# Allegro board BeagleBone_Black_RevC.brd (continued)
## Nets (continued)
MII1_RXD0: R128.1 U5.M16
MII1_RXD1: R127.1 U5.L15
MII1_RXD2: R126.1 U5.L16
MII1_RXD3: R125.1 U5.L17
MII1_RXDV: R129.1 U5.J17
MII1_RXERR: R133.1 U5.J15
MII1_TXCLK: R134.1 U5.K18
MII1_TXD0: R39.1 U5.K17
MII1_TXD1: R40.1 U5.K16
MII1_TXD2: R41.1 U5.K15
MII1_TXD3: R42.1 U5.J18
MII1_TXEN: R38.1 U5.J16
MMC0_CD: P2.19 P10.10 R157.1 U5.C15
MMC0_CLKO: R16.1 U5.G17
MMC0_CMD: R15.1 U5.G18
MMC0_DAT0: R31.1 U5.G16
MMC0_DAT1: R32.1 U5.G15
MMC0_DAT2: R2.1 U5.F18
MMC0_DAT3: R13.1 U5.F17
MMC1_CLK: C175.1 P8.21 R35.2 R110.2 U13.M6
MMC1_CMD: P8.20 R36.2 R109.2 U13.M5
MMC1_DAT0: P8.25 R43.2 R101.2 U13.A3
MMC1_DAT1: P8.24 R44.2 R102.2 U13.A4
MMC1_DAT2: P8.5 R103.2 R168.2 U13.A5
MMC1_DAT3: P8.6 R104.2 R169.2 U13.B2
MMC1_DAT4: P8.23 R105.2 R170.2 U13.B3
MMC1_DAT5: P8.22 R106.2 R171.2 U13.B4
MMC1_DAT6: P8.3 R107.2 R172.2 U13.B5
MMC1_DAT7: P8.4 R108.2 R173.2 U13.B6
MODE2: R113.1 R138.2 U14.15
OSC0_IN: C25.1 R17.1 U5.V10 Y2.2
OSC0_OUT: C26.1 R17.2 U5.U11 Y2.1
OSC1_IN: C21.2 U5.A6 Y1.1
OSC1_OUT: C22.2 U5.A4 Y1.4
P_BYPASS: C4.2 U2.47
P_INT_LDO: C3.2 U2.48
P_L1: L1.1 U2.20
P_L2: L2.1 U2.23
P_L3: L3.1 U2.31
PHY_VDDCR: C134.1 C136.1 U14.6
PHY_XTAL1: C143.1 R141.2 R142.1 Y3.1
PHY_XTAL2: R141.1 R143.1 U14.4(XTAL2)
PHYX: C142.1 R143.2 Y3.2
PMIC_INT: R1.2 U2.45 U5.B18
PMIC_PGOOD: U2.26 U5.B15 U16.2
PMIC_POWR_EN: U2.9 U5.C6
PROC_A15: R18.1 U5.A15
PWR_BUT: P9.9 S3.2 S3.4(B2) U2.25
PWR_LEDR: D1.1(C) R12.2
RBIAS: R144.1 U14.32
RCLKIN: R140.2 R142.2 U14.5
REFCLKO: R118.1 R124.2 R131.2 U14.7
RXD0/MODE0: R112.1 R128.2 U14.11
RXD1/MODE1: R114.1 R127.2 U14.10
RXD2/RMIISEL: R117.1 R126.2 U14.9
RXD3/PHYAD2: R116.1 R125.2 U14.8
RXDV: R129.2 U14.26
RXER/PHYAD0: R115.1 R133.2 U14.13
RXN: C138.1 P5.2 R121.1 U14.30
RXP: C137.1 P5.1 R120.1 U14.31
SD_CLK: C5.1 P10.5 R16.2 R152.2
SD_CMD: P10.3 R15.2 R151.2
SD_DAT0: P10.7 R31.2 R153.2
SD_DAT1: P10.8 R32.2 R154.2
SD_DAT2: P10.1 R2.2 R150.2
SD_DAT3: P10.2 R13.2 R155.2
SPI1_CS0: P9.28 U5.C12 U11.25
SPI1_D0: P9.29 U5.B13 U11.24
SPI1_D1: P9.30 U5.D12
SPI1_SCLK: P9.31 U5.A13 U11.23
SYS_5V: C7.2 C8.2 C10.2 C13.2 C17.1 C34.1 P9.7 P9.8 R71.1 R72.1 R73.1 R74.1 RT1.1 U2.2 U2.7 U2.8 U2.21 U2.22 U2.32 U2.39 U2.42 U4.2 U8.2 U8.3
SYS_RESETN: C24.1 C30.1 P2.15 P9.10 R14.2 S1.2 S1.4(B2) U1.2 U5.A10 U16.4(Y)
TCT_RCT: C141.1 P5.4 P5.5 R137.1
TESTOUT: TP3.1(TP) U5.A3
TIMER4: P8.7 U5.R7
TIMER5: P8.9 U5.T6
TIMER6: P8.10 U5.U6
TIMER7: P8.8 U5.T7
TXCLK: R134.2 U14.20
TXD0: R39.2 U14.22
TXD1: R40.2 U14.23
TXD2: R41.2 U14.24
TXD3: R42.2 U14.25
TXEN: R38.2 U14.21
TXN: C140.1 P5.6 R123.1 U14.28
TXP: C139.1 P5.3 R122.1 U14.29
U5_H18: R28.1 U5.H18
U5_R13: R160.1 U5.R13
U5_T13: R161.1 U5.T13
UART0_RX: U5.E15 U15.6
UART0_TX: U5.E16 U15.5
UART1_RXD: P9.26 U5.D16
UART1_TXD: P9.24 U5.D15
UART2_RXD: P9.22 U5.A17
UART2_TXD: P9.21 U5.B17
UART4_RXD: P9.11 U5.T17
UART4_TXD: P9.13 U5.U17
USB0_DM: P4.2 U5.N18 U10.2
USB0_DP: P4.3 U5.N17 U10.1
USB0_ID: P4.4 U5.P16 U10.3
USB1_DM: P3.2 U5.R18 U9.2
USB1_DP: P3.3 U5.R17 U9.1
USB1_DRVVBUS: R53.1 U5.F15 U8.4
USB1_ID: R49.2 U5.P17
USB1_OCN: R52.2 U5.T16 U8.5
USB1_PWR: C35.1 FB7.1 R37.2 U8.6 U8.7 U8.8 U9.6(VBUS)
USB1_VBUS: R37.1 U5.T18
USB_DC: C1.2 C36.1 P4.1(VB) R159.1 U2.12 U10.6(VBUS)
USR0: Q1.2 R76.1 U5.V15
USR1: Q1.5 R77.1 U5.U15
USR2: Q2.2 R78.1 U5.T15
USR3: Q2.5 R79.1 U5.V16
VDCDC1: L1.2 R6.1 U2.19
VIO: R7.2 U2.18 U16.5
VLDO1: R5.1 R7.1 R8.1 U2.3
VREFP_ADC: C31.1 C32.1 C33.1 R27.2 U5.B9
VRTC: C16.1 C105.1 R5.2 R26.1 U5.D7
WAKEUP: R26.2 U2.13(WAKEUP) U5.C5
WP: R156.2 TP4.1(TP) U7.5(WP)
XDMA_EVENT_INTR0: P2.17 R18.2 U6.1
YEL_C: P5.11(YELC) R130.2
YELA: P5.12 R135.1 U14.2
ZQ: R99.2 U12.L8(ZQ)
N21667305: R149.1 U11.49
N21757673: C19.1 R10.1 R11.2 U4.4
N21769115: R75.2 S2.1 S2.3
N22155575: R159.2 U5.P15
N22248684: R167.1 Y4.3
N22248838: R21.1 U6.5
N22287501: R162.1 U3.4(Y)
N22287555: U3.2 U5.R14
N22420400: TP5.1(TP) U2.4 U2.5
N22420444: TP6.1(TP) U2.6
N22420447: TP7.1(TP) U2.11
N22488252: TP9.1(TP) U5.E17

Pads without a net: D6 6 7 9 10; D7 6 7 9 10; J1 2 3 6; NOREF 1; NOREF#3 1; NOREF#14 1; NOREF#26 1; NOREF#27 1; NOREF#29 1; P1 3; P2 6; P5 7; P6 2; P10 S2; U2 14 15 16 17 33 34 35 36 37 38 44; U3 1; U5 F16 M5 M15 P18; U9 3 5; U10 5; U11 26 28; U12 J1 J9 L1 L9; U13 A1 A2 A7 A8 A9 A10 A11 A12 A13 A14 B1 B7 B8 B9 B10 B11 B12 B13 B14 C1 C3 C5 C7 C8 C9 C10 C11 C12 C13 C14 D1 D2 D3 D4 D12 D13 D14 E1 E2 E3 E5 E8 E9 E10 E12 E13 E14 F1 F2 F3 F10 F12 F13 F14 G1 G2 G3 G10 G12 G13 G14 H1 H2 H3 H5 H12 H13 H14 J1 J2 J3 J12 J13 J14 K1 K2 K3 K6 K7 K10 K12 K13 K14 L1 L2 L3 L12 L13 L14 M1 M2 M3 M7 M8 M9 M10 M11 M12 M13 M14 N1 N3 N6 N7 N8 N9 N10 N11 N12 N13 N14 P1 P2 P7 P8 P9 P10 P11 P12 P13 P14; U16 1; Y1 2 3

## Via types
v1: diameter 0.457, hole 0.203, TOP to BOTTOM, 801 vias
v2: diameter 0.254, hole 0.152, TOP to BOTTOM, 29 vias
v3: diameter 0.559, hole 0.305, TOP to BOTTOM, 30 vias

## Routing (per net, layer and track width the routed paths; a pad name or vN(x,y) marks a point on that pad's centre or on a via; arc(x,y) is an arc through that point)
DGND: length 496.4
  TOP w0.121: U13.N2 v2(26.85,44.91)
  TOP w0.191: R118.2 31.43,26.48 32.95,26.48 v1(33.02,26.54) ; U10.4 v1(14.1,41.41)
  TOP w0.203: v3(23.88,15.24) 24.26,15.24 24.46,15.04 U2.30 ; U13.K8 v2(28.09,41.66) ; v1(12.37,44.77) Q1.1 12.37,46.21 12.51,46.35 13.53,46.35 13.67,46.5 Q1.4 ; U2.41 v1(23.46,19.62) ; U13.A6 33.54,42.66 33.66,42.55 33.66,41.27 v1(34.29,40.64) ; U13.J5 29.46,42.8 29.73,42.8 U13.G5 v2(30.09,43.66) ; Q2.4 10.17,46.5 10.03,46.35 9.02,46.35 8.88,46.21 Q2.1 v1(8.88,44.77) ; U13.C4 v2(31.6,43.16) ; U13.E7 v2(31.6,42.16) ; v2(26.04,43.66) U13.P4 ; U13.P6 v2(26.05,42.66) ; U13.N5 v2(26.85,43.41) ; U13.H10 v2(29.6,40.13)
  TOP w0.254: U5.L10 v1(44.92,30.01) ; v1(44.92,30.01) U5.K10 ; v1(44.92,30.01) U5.K11 ; v1(60.7,27.17) U12.E1 60.18,27.69 59.69,27.69 59.31,27.3 59.31,26.96 U12.G1 ; U5.L13 v1(43.32,30.81) U5.L12 ; U5.H7 v1(48.12,27.61) ; v3(65.41,41.91) 65.25,42.06 U11.53 ; U12.D1 v1(60.7,27.97) U12.E2 ; U5.M8 v1(46.52,31.61) U5.M9 ; v1(66.3,23.96) U12.J8 ; v1(66.3,27.97) U12.E8 ; v1(43.32,26.81) U5.G12 43.88,27.05 44.36,27.05 U5.G11 ; U5.M7 v1(48.12,30.81) U5.M6 ; v1(75.06,39.62) 74.93,39.5 74.55,39.5 74.42,39.37 D7.3 ; U5.J6 v1(48.92,28.41) U5.H6 ; U11.16 59.15,35.65 ; 59.15,35.65 U11.17 ; 59.15,35.65 59.05,35.56 v1(58.42,35.56) ; U5.N14 v1(41.72,31.61) U5.M14 ; D7.8 v1(78.99,39.37) ; U12.B9 v1(67.1,30.37) U12.A9 ; U5.N10 v1(44.92,32.41) U5.N11 ; v1(59.9,30.37) U12.B1 ; v1(59.9,21.56) U12.M1 ; D6.8 v1(78.99,34.92) ; v1(46.52,30.01) U5.K9 ; v1(67.1,19.96) U12.P9 ; v1(66.3,28.77) U12.D8 ; U11.8 61.21,40.25 v3(61.59,40.64) ; v1(44.92,31.61) U5.M10 ; U5.A1 v1(52.52,21.72) ; U5.G9 v1(46.52,26.81) U5.F8 ; v1(59.9,18.36) U12.T1 ; v1(67.1,18.36) U12.T9 ; v1(66.3,26.37) U12.G8 ; U11.9 61.21,39.76 v3(61.59,39.37) ; v1(67.1,21.56) U12.M9 ; v3(64.14,41.91) 64.75,42.52 U11.54 ; U5.H10 v1(44.92,28.41) U5.J10 ; v1(43.32,27.61) U5.H12 ; U5.A18 v1(38.52,22.01) ; U11.18 60.25,35 v1(60.45,34.8) 60.45,34.82 60.75,35.12 U11.19 ; U5.H9 v1(46.52,27.61) U5.G8 ; v3(61.59,41.91) 61.59,42.93 61.25,43.27 U11.61 ; v3(61.59,41.91) 60.75,42.76 U11.62 ; v3(61.59,41.91) 60.71,41.91 60.25,42.37 U11.63 ; U5.J11 v1(44.12,28.41) ; v1(47.32,28.41) U5.J8 ; U12.F9 v1(67.1,26.37) U12.G9 ; U5.M12 v1(44.12,30.81) U5.L11 ; D6.3 72.52,34.92 72.39,34.8 v1(72.01,34.8) ; v1(61.5,30.37) U12.B3 ; v1(47.32,27.61) U5.H8 ; v1(46.52,28.41) U5.J9 ; v1(59.9,19.96) U12.P1 ; v1(60.7,23.96) U12.J2 ; v1(48.12,32.41) U5.N7 ; U5.K7 U5.J7 v1(48.12,28.41) ; U5.V1 v1(52.52,36.7) ; U5.V18 v1(38.1,36.01)
  TOP w0.381: R93.2 R94.2 R95.2 v1(71.75,45.72) ; R93.2 R92.2 R91.2 R90.2 R89.2 R88.2 R87.2 R86.2 R85.2 R83.2 R82.2 R84.2 ; R93.2 v1(69.85,45.72) ; 14.92,19.37 C3.1 C18.2 C16.2 ; v1(34.29,6.48) C29.2 ; C169.2 56.9,36.83 57.15,37.08 v1(57.15,37.34) ; S1.1 v1(9.02,52.24) ; U3.3 v1(40.97,45.85) ; S2.4 S2.2 v1(78.49,42.38) ; v1(56.52,48.26) C57.1 56.13,47.5 55.88,47.24 55.88,46.74 55.63,46.48 C165.2 53.72,46.48 52.7,45.47 C168.2 ; R84.2 R80.2 R81.2 v1(57.47,45.72) ; R84.2 v1(59.37,45.72) ; C173.2 v1(74.68,46.48) ; Y4.2 41.71,40.82 ; Y4.2 40.56,40.82 ; Y4.2 41.15,41.53 ; S1.3 v1(6.86,52.24) ; v1(6.99,17.14) R10.2 C19.2 ; v1(56.26,11.68) 55.63,11.68 C155.1 C96.1 ; v1(53.98,42.67) C167.2 54.36,43.43 54.61,43.69 54.61,44.2 54.86,44.45 C156.2 ; C61.1 v1(72.71,48.26) ; C5.2 R118.2 ; 46.86,43.05 v1(46.86,43.7) ; v1(29.46,20.7) 28.77,21.4 C37.2 ; v1(45.09,12.7) C27.2 R165.2 ; C166.2 v1(52.7,41.66) ; S3.1 v1(7.62,42.71) S3.3 ; R29.2 v1(44.96,43.56) ; v1(55.24,39.12) C160.2 55.63,39.88 55.88,40.13 55.88,40.64 56.13,40.89 C163.2 ; v1(53.98,41.66) C157.2 ; U16.3 30.64,9.69 v1(30.16,10.16) ; R25.2 36.39,9.08 36.07,8.76 v1(36.07,8.57) ; v1(22.35,7.11) 22.35,8.51 C9.1 22.99,8 v1(22.99,7.11) v1(22.35,7.11) ; C12.1 24.83,8.45 v1(24.83,7.11) v1(24.19,7.11) 24.19,8.06 C12.1
  TOP w0.508: v1(29.97,18.03) v1(29.97,17.4) 29.97,16.13 ; v1(64.52,15.49) 64.52,13.78 C34.2 63.63,13.91 v1(63.63,15.49)
  TOP w0.635: 14.92,19.37 v1(13.97,19.37) C1.1
  TOP w0.762: C11.1 C55.1
  LYR2_GND w0.889: 4.09,9.53 P1.2 ; P1.2 5.18,11.63 ; P1.2 6.27,9.53 ; P1.2 5.18,7.42 ; 16.41,24.67 P5.8 ; P5.8 17.88,26.13 ; P5.8 16.41,26.13 ; P5.8 17.88,24.67 ; P9.46 76.3,3.71 ; P9.46 74.83,5.18 ; P9.46 76.3,5.18 ; P9.46 74.83,3.71 ; P8.1 20.65,51.13 ; P8.1 18.72,49.2 ; P8.1 18.72,51.13 ; P8.1 20.65,49.2 ; 18.95,3.71 P9.2 ; P9.2 20.42,5.18 ; P9.2 18.95,5.18 ; P9.2 20.42,3.71 ; 41.58,6.65 J1.1 ; J1.1 43.51,6.65 ; J1.1 41.58,8.59 ; 18.72,2.87 P9.1 20.65,2.87 ; P3.4 74.12,19.56 ; P3.4 74.12,21.11 ; P3.4 72.56,21.11 ; P3.4 72.56,19.56 ; 16.54,8.86 TP8.1 ; TP8.1 18.01,7.39 ; TP8.1 16.54,7.39 ; TP8.1 18.01,8.86 ; TP1.1 59.79,11.53 ; TP1.1 58.32,10.06 ; TP1.1 59.79,10.06 ; TP1.1 58.32,11.53 ; 72.29,3.71 P9.44 ; P9.44 73.76,5.18 ; P9.44 73.76,3.71 ; P9.44 72.29,5.18 ; 73.76,2.64 P9.43 72.29,2.64 ; 74.83,2.64 P9.45 76.3,2.64 ; 20.42,51.97 P8.2 18.95,51.97
  BOTTOM w0.191: 79.89,25.75 P6.13 79.16,25.75 v1(78.99,25.91) ; R115.2 30.99,32.1 30.86,32.23 29.34,32.23 29.21,32.35 v1(29.21,32.7) ; v1(82.8,26.73) 82.11,26.73 81.72,26.35 P6.16 ; 79.89,24.55 P6.7 v1(78.99,24.55) ; P6.4 81.72,23.95 82.04,23.62 v1(82.8,23.62) ; v1(44.92,24.41) 44.92,24.3 45.71,23.5 C88.2 ; P6.10 v1(82.8,25.15)
  BOTTOM w0.203: C100.2 48.81,25.94 49.26,25.5 49.43,25.5 v1(49.72,25.21) ; C135.2 26.92,33.91 26.92,36.2 26.29,36.83 25.74,36.83 25.27,37.3 C174.2
  BOTTOM w0.254: C130.2 v1(34.29,40.64) ; v2(31.6,42.16) 31.6,41.88 31.11,41.4 C129.2 ; U15.1 50.28,10.68 50.04,10.92 50.04,11.94 50.28,12.18 U15.4 52.08,12.18 52.83,11.43 52.83,10.54 53.21,10.16 v1(54.48,10.16) ; U6.4 44.79,12.41 v1(45.09,12.7) ; C127.2 v1(25.4,40.64) ; v2(28.09,41.66) 28.09,41.94 28.57,42.42 C128.2 ; C70.1 42.63,26.12 v1(43.32,26.81) v1(43.32,27.61) ; C155.1 56.01,11.94 v1(56.26,11.68)
  BOTTOM w0.305: U9.4 80.48,18.91 v1(80.62,19.05) ; C46.2 44.63,29.72 v1(44.92,30.01) ; C48.2 47.83,28.7 v1(48.12,28.41) ; C98.2 48.92,29.1 v1(48.92,28.41) ; C73.1 v1(48.12,32.41) 47.43,32.41 C43.2 ; C50.2 v1(47.32,27.61) ; v1(43.32,26.81) 44.01,26.81 C63.2 ; C72.1 46.23,26.52 v1(46.52,26.81) ; v1(46.52,31.61) 46.23,31.9 C42.2 ; C94.2 v1(44.12,30.81) ; v1(46.52,30.01) 45.83,30.01 C47.2 ; C49.2 45.58,28.41 v1(44.92,28.41) ; C99.2 v1(48.12,27.61) ; v1(48.12,30.81) C97.2 ; C41.2 41.72,32.3 v1(41.72,31.61) 41.72,30.92 C66.2 ; C60.1 v1(43.32,27.61)
  BOTTOM w0.381: C132.2 24.77,29.84 v3(25.08,30.16) 25.4,29.84 C136.2 C134.2 ; C132.2 C131.2 ; C132.2 24,30.99 v3(24.13,31.11) ; v1(8.88,44.77) 8.88,45.86 ; 8.88,45.86 7.23,45.86 7.11,45.73 P4.5 ; 8.88,45.86 8.88,46.56 ; v1(72.01,34.8) 71.77,34.56 P10.6 ; v3(25.08,32.07) 24.77,32.07 24.38,32.45 C133.1 ; C108.2 v1(57.15,29.57) ; C59.2 C90.2 C91.2 C89.2 C105.2 C92.2 ; C40.1 33.02,28.07 v1(33.02,27.37) 33.02,26.99 ; C40.1 33.78,28.07 C52.2 ; C40.1 33.78,28.83 C51.2 ; 8.88,46.56 8.88,47.37 8.85,47.4 v1(8.85,49.11) ; 8.88,46.56 8.89,46.55 R78.2 ; C23.2 v1(24.63,39.12) ; U8.1 v1(75.56,13.63) ; C161.2 C166.2 v1(52.7,41.66) ; C145.2 58.93,35.56 v1(58.42,35.56) ; R148.2 C151.2 66.42,35.69 66.04,36.07 66.04,36.32 65.66,36.7 C147.2 v3(65.41,38.1) ; C149.2 68.33,44.7 v1(68.58,44.7) ; 33.02,20.33 33.02,21.21 C62.1 33.78,21.21 33.78,20.33 ; 33.02,20.33 33.78,20.33 ; 33.02,20.33 v1(33.02,20.32) ; v1(6.22,29.46) v1(6.22,30.23) ; v1(6.22,29.46) 5.4,29.46 R136.1 5.4,30.23 v1(6.22,30.23) ; v1(6.22,29.46) R130.1 R135.2 ; v1(6.22,30.23) R132.1 ; v1(36.89,23.18) 36.89,23.18 37.21,22.86 C85.2 C83.2 C82.2 ; v3(64.14,41.91) 64.14,43.31 65.41,43.31 ; v1(47.32,38.1) C81.2 ; C78.2 35.05,33.91 v1(35.56,33.91) ; R12.1 4.83,16.51 5.46,17.14 v1(6.99,17.14) R10.2 ; C173.2 v1(74.68,46.48) ; U1.3 30.17,37.21 30.59,37.21 30.61,37.19 v1(30.71,37.19) ; v1(53.98,41.66) C157.2 C172.2 ; C24.2 C30.2 v1(30.16,10.16) ; v1(36.83,30.81) C87.2 C45.2 ; R96.1 v1(69.85,23.16) 70.36,23.16 70.41,23.11 C153.2 ; C140.2 v1(10.67,27.94) ; R53.2 v1(76.81,19.68) ; R117.2 R116.2 v1(31.75,27.94) ; C71.1 38.61,36.32 38.3,36.01 v1(38.1,36.01) 37.81,36.01 37.61,35.81 C86.2 ; C92.2 C104.2 v1(49.21,18.41) ; C92.2 v1(48.26,18.41) ; C139.2 v1(10.67,31.75) ; C152.2 v1(26.04,23.11) ; C154.2 70.45,26.16 ; C143.2 27.11,26.35 v1(28.26,26.35) ; C119.2 v1(69.85,24.36) ; R77.2 13.9,45.53 13.65,45.78 13.65,46.29 13.4,46.55 R76.2 12.6,46.55 12.37,46.32 v1(12.37,44.77) ; C54.2 C44.2 ; C54.2 C79.2 C69.1 ; C54.2 v1(36.83,26.81) ; v1(29.46,20.7) 29.46,21.46 29.91,21.91 U7.2 ; v1(49.21,18.41) 50.87,18.41 51.12,18.66 R54.1 ; v1(49.21,18.41) R164.2 ; C118.1 68.83,32.13 C114.2 68.83,30.35 69.09,30.1 C115.2 v1(69.85,29.57) 71.35,29.57 P10.9 ; C80.2 41.32,37.78 41.42,37.88 41.42,38.25 v1(41.53,38.35) ; C135.2 v1(28.45,33.66) ; C64.2 33.78,20.33 ; C113.2 v1(57.15,19.16) ; C39.1 33.78,25.15 C53.2 33.03,24.13 v1(32.89,24.27) ; C39.1 33.78,25.91 C52.2 ; C39.1 33.02,25.91 v1(33.02,26.54) 33.02,26.99 ; C125.2 v1(32.38,48.26) ; v1(66.3,23.96) U12.J8 C123.2 ; C121.2 v1(69.85,19.16) ; v1(33.02,35.56) C67.2 C38.2 ; C84.2 37.19,32.41 36.83,32.77 v1(36.83,33.15) 36.83,33.66 37.15,33.97 R49.1 ; C111.2 v1(57.15,23.16) ; C122.1 69.84,16.83 v1(69.85,16.82) ; P2.20 39.56,18.73 40.53,17.76 40.53,16.27 40.24,15.98 39.5,15.98 39.35,16.13 38.01,16.13 P2.16 v1(36.07,16.19) ; P2.8 36.13,11.11 v1(36.07,11.18) 36.07,12.13 36.32,12.38 P2.10 P2.12 ; C107.2 v1(57.15,31.17) ; 66.67,43.31 65.41,43.31 ; 65.41,43.31 v3(65.41,41.91) ; R99.1 v1(69.85,21.96) ; C58.2 C106.2 43.96,37.32 44.32,36.96 v1(45.72,36.96) C56.1 ; v1(10.79,44.77) R79.2 ; C126.1 v1(23.5,39.88) ; C120.2 v1(69.85,20.76) ; C141.2 v1(10.67,30.48) ; v1(40.97,45.85) 40.97,47.04 40.51,47.5 C158.2 ; v3(65.41,40.64) 65.66,40.39 C150.2 ; C117.2 v1(69.85,25.57) ; R22.1 v1(57.15,28.41) ; C52.2 33.02,26.99 ; P2.4 v1(36.07,8.57) ; C109.2 v1(57.15,27.17) C28.2 ; C164.2 v1(50.16,41.66) ; C74.1 50.52,37.74 v1(50.16,38.1) ; R145.2 v1(31.75,34.61) ; C57.1 v1(56.52,48.26) ; C101.2 52.07,18.67 52.32,18.41 v1(52.83,18.41) 53.72,18.41 C95.1 53.66,17.84 C102.2 C103.2 55.31,16.7 v1(55.37,16.76) ; C159.2 39.69,40.51 v1(40.32,39.88) ; C142.2 23.05,26.35 v1(21.91,26.35) ; C35.2 v1(81.89,19.68) ; C138.2 v1(10.67,33.02) ; C68.1 v1(48.92,38.1) ; v1(32.38,37.15) C77.2 ; C137.2 v1(10.67,34.29) ; R144.2 v1(18.73,28.26) ; C144.2 61.09,40.13 v3(61.59,40.64) ; C17.2 v1(6.99,15.88) ; C112.2 v1(57.15,20.76) ; C110.2 v1(57.15,25.57) ; v1(62.99,21.21) C124.2 R100.2 ; C61.1 v1(72.71,48.26) ; v1(14.1,41.41) 14.09,41.4 ; C116.2 v1(69.85,27.97) ; v1(44.2,14.1) v1(43.43,14.1) 43.43,14.86 FB3.2 44.2,14.86 v1(44.2,14.1)
  BOTTOM w0.508: C36.2 13.04,42.52 v1(12.34,43.22)
  BOTTOM w0.635: 16.45,14.61 14.22,14.61 13.97,14.86 13.97,15.88 ; 13.97,17.14 13.97,15.88 ; 13.97,17.14 16.45,17.14 ; 13.97,17.14 13.97,18.41 ; 13.97,15.88 U4.7 ; v1(13.97,19.37) 13.97,18.41 ; 13.97,18.41 U4.5 ; C2.1 5.71,12.45 5.18,11.91 P1.2
  BOTTOM w0.762: P9.1 P9.2 ; P9.45 P9.46 ; P8.1 P8.2
  vias: v1(7.79,48.97) v3(21.34,15.24) v3(21.34,13.97) v3(22.61,15.24) v3(22.61,13.97) v3(25.08,31.11) v3(26.04,31.11) v3(61.59,38.1) v3(62.87,41.91) v3(62.87,40.64) v3(62.87,39.37) v3(62.87,38.1) v3(64.14,40.64) v3(64.14,39.37) v3(64.14,38.1) v3(65.41,39.37) v3(78.71,15.24) v3(78.71,13.97) v3(79.98,15.24) v3(79.98,13.97)
GND_EARTH: length 144.8
  TOP w0.889: MTG3.1 16.37,53.2 ; MTG3.1 12.84,53.2 ; MTG3.1 12.84,49.67 ; MTG3.1 16.37,49.67 ; MTG1.1 16.37,4.94 ; MTG1.1 16.37,1.41 ; MTG1.1 12.84,4.94 ; MTG1.1 12.84,1.41 ; 78.88,50.03 MTG4.1 ; MTG4.1 78.88,46.49 ; MTG4.1 82.41,46.49 ; 78.88,8.12 MTG2.1 ; MTG2.1 78.88,4.58 ; MTG2.1 82.41,8.12
  LYR2_GND w0.889: 78.88,4.58 MTG2.1 ; MTG2.1 78.88,8.12 ; MTG2.1 82.41,8.12 ; MTG3.1 16.37,49.67 ; MTG3.1 12.84,49.67 ; MTG3.1 12.84,53.2 ; MTG3.1 16.37,53.2 ; 12.84,4.94 MTG1.1 ; MTG1.1 12.84,1.41 ; MTG1.1 16.37,1.41 ; MTG1.1 16.37,4.94 ; 78.88,50.03 MTG4.1 ; MTG4.1 82.41,46.49 ; MTG4.1 78.88,46.49
  LYR5_PWR w0.889: MTG3.1 16.37,53.2 ; MTG3.1 16.37,49.67 ; MTG3.1 12.84,49.67 ; MTG3.1 12.84,53.2 ; 12.84,1.41 MTG1.1 ; MTG1.1 12.84,4.94 ; MTG1.1 16.37,4.94 ; MTG1.1 16.37,1.41 ; 78.88,50.03 MTG4.1 ; MTG4.1 78.88,46.49 ; MTG4.1 82.41,46.49 ; 78.88,4.58 MTG2.1 ; MTG2.1 78.88,8.12 ; MTG2.1 82.41,8.12
  BOTTOM w0.381: v1(1.91,30.23) 2.86,30.23 R136.2 2.86,29.46 v1(1.91,29.46)
  BOTTOM w0.635: P10.S1 75.97,43.71 77.72,45.47
  BOTTOM w0.889: 78.88,8.12 MTG2.1 ; MTG2.1 82.41,8.12 ; MTG2.1 78.88,4.58 ; MTG4.1 82.41,46.49 ; MTG4.1 78.88,46.49 ; MTG4.1 78.88,50.03 ; 12.84,1.41 MTG1.1 16.37,1.41 ; 84.96,44.96 P10.S4 85.39,42.84 ; 85.39,31.46 P10.S3 85.39,29.56 ; 16.37,53.2 MTG3.1 12.84,53.2
GND_OSC0: length 40
  TOP w0.381: v1(44.13,39.88) R29.1 44.96,39.12 44.32,38.48 44.32,36.68 44.52,36.48 U5.V11
  LYR4 w0.381: v1(52.83,17.78) 53.34,17.78 55.5,19.94 55.5,38.1 53.72,39.88 v1(44.13,39.88)
  BOTTOM w0.381: v1(52.83,17.78) 52.7,17.65 R30.1
GND_OSC1: length 11.3
  TOP w0.254: U5.A5 49.32,22.18 50.04,21.46 50.04,19.3 51.12,18.22 v1(51.12,17.78)
  BOTTOM w0.381: C22.1 R30.2 ; C22.1 51.12,15.68 ; C22.1 v1(51.75,14.86) ; 51.12,15.68 v1(51.12,17.78) ; 51.12,15.68 C21.1 v1(50.48,14.86)
GNDA_ADC: length 46.8
  TOP w0.254: v1(47.32,25.21) U5.E8
  TOP w0.305: 46.12,21.97 U5.A9
  TOP w0.381: C93.2 v1(45.09,16.51) ; C93.2 45.85,17.27 46.48,17.91 46.48,21.59 46.12,21.95 46.12,21.97 ; C93.2 C33.2 C31.2 C32.2
  LYR4 w0.381: P9.34 59.05,3.17 57.28,3.17 56.52,3.94 56.52,8.13 55.88,8.76 53.85,8.76 46.1,16.51 v1(45.09,16.51) 45.09,18.92 46.48,20.32 46.48,22.61 45.85,23.24 45.85,24.77 46.29,25.21 v1(47.32,25.21)
  BOTTOM w0.381: FB3.1 44.84,17.14 45.09,16.89 v1(45.09,16.51)
VBUS: length 5.3
  BOTTOM w0.508: FB7.2 71.18,11.18 P3.1
VDD_1V8: length 39.8
  TOP w0.203: 24.27,19.81 23.82,19.36 23.82,18.87 23.86,18.83 U2.40
  TOP w0.254: v1(40.12,32.41) U5.N16 ; U5.E9 U5.D10 v1(44.92,25.21) ; v1(40.12,34.01) U5.R16
  TOP w0.381: v1(26.92,17.72) v1(26.92,18.35) 25.46,19.81 24.27,19.81 23.77,20.32 13.34,20.32 11.94,18.92 R9.2
  LYR3 w0.381: v1(26.92,17.72) v1(26.92,18.35)
  BOTTOM w0.305: C86.1 38.89,35.24 v1(40.12,34.01) ; v1(44.92,25.21) 45.61,24.52 C88.1
  BOTTOM w0.381: FB1.1 33.02,32.39 v1(33.02,33.27) 33.4,33.27 C78.1 33.53,33.91 v1(33.02,33.91) ; v1(54.48,35.56) 55.56,35.56 FB5.2 55.57,36.2 v1(54.48,36.2) ; v1(26.92,17.72) 26.04,17.72 C14.2 26.04,18.35 v1(26.92,18.35) v1(26.92,17.72) ; 45.34,15.24 FB2.2 46.35,14.35 46.1,14.1 v1(45.85,14.1) v1(45.09,14.1) 45.09,14.99 45.34,15.24
VDD_3V3A: length 128
  TOP w0.203: v1(22.36,19.62) 22.36,19.11 22.66,18.81 U2.43
  TOP w0.254: v1(40.92,34.01) U5.R15 ; U5.P10 v1(44.92,33.21) U5.P11 ; v1(48.12,33.21) U5.P7 U5.P8 ; U5.P6 v1(48.92,33.21) ; U5.K14 v1(42.52,30.01) U5.L14 ; U5.F14 v1(41.72,26.81) U5.G14 ; U5.E13 v1(43.32,25.21) U5.E12 v1(44.12,25.21) U5.E11 v1(44.92,26.01) U5.E10 ; U5.P12 v1(43.32,33.21) ; U5.H14 v1(41.72,28.41) U5.J14 ; v1(40.92,32.41) U5.N15 ; U5.N5 v1(49.72,31.61) ; U5.P5 v1(49.72,33.21) ; U5.P13 v1(42.52,33.21)
  TOP w0.381: C61.2 v1(72.71,45.72) ; v1(39.69,45.72) 39.69,45.73 39.67,45.75 U3.5 ; C57.2 v1(56.52,45.72) ; v1(26.99,23.11) R4.1 ; R4.1 R3.1 ; R4.1 C37.1 ; C27.1 v1(45.09,10.16) ; Y4.4 39.5,42.99 v1(39.69,43.18)
  LYR4 w0.381: v1(70.8,45.72) 70.17,45.09 70.17,39.56 72.77,36.96 72.77,29.34 74.55,27.56 74.55,25.15 73.66,24.26 73.66,21.97 75.18,20.45 82.4,20.45 v1(83.16,19.68)
  BOTTOM w0.254: U6.6 45.28,11.76 45.09,11.56 45.09,11.1 ; 45.09,10.45 v1(45.09,10.16) ; 45.09,10.45 45.09,11.1 ; 45.09,10.45 U6.8 ; 45.09,11.1 U6.7
  BOTTOM w0.305: C56.2 45.61,33.9 v1(44.92,33.21) ; C87.1 39.21,30.81 39.81,31.41 39.92,31.41 v1(40.92,32.41) ; C66.1 42.63,30.12 v1(42.52,30.01) ; C70.2 41.72,26.12 v1(41.72,26.81) 41.72,27.5 C60.2 41.72,27.72 v1(41.72,28.41) ; C72.2 45.43,25.5 v1(44.92,26.01)
  BOTTOM w0.381: R156.1 C152.1 26.99,21.4 ; R67.1 R66.1 R65.1 R64.1 R63.1 R62.1 R61.1 R60.1 R58.1 R57.1 R59.1 R55.1 ; R67.1 R68.1 R69.1 ; R67.1 v1(68.9,45.72) ; v1(36.08,37.59) 35.62,37.59 C77.1 ; C71.2 v1(36.83,36.83) ; v1(39.69,45.72) C158.1 ; R14.1 v1(30.16,12.06) ; v1(26.99,23.11) 26.99,21.4 ; 26.99,21.4 27.43,20.95 U7.4 ; C38.1 C67.1 ; C67.1 34.8,36.77 C77.1 ; C67.1 v1(35.56,35.56) ; R52.1 v1(83.16,19.68) ; C73.2 49.83,31.72 v1(49.72,31.61) ; R69.1 R70.1 C61.2 v1(72.71,45.72) ; R69.1 v1(70.8,45.72) ; R55.1 R56.1 C57.2 v1(56.52,45.72) ; R55.1 v1(58.42,45.72) ; v1(22.36,19.62) 22.36,19.25 21.91,18.8 C15.2 ; v1(21.59,23.11) R1.1 20.89,22.42 20.45,21.97 15.37,21.97 12.17,18.77 12.17,14.84 11.94,14.61 10.86,14.61 ; C77.1 35.5,36.83 v1(36.08,36.83) ; C59.1 v1(43.5,20.95) ; C159.1 v1(39.69,43.18)
VDD_3V3AUX: length 19.6
  TOP w0.121: D1.2 v1(5.59,15.88) ; U2.1 19.79,17.81 19.18,18.41 v1(18.8,18.41) C18.1
  LYR3 w0.133: v1(5.59,15.88) 5.59,17.02 6.35,17.78 10.54,17.78 11.18,18.41 v1(18.8,18.41)
VDD_3V3B: length 118.4
  TOP w0.203: U13.K9 v2(28.09,41.16) ; v2(26.04,44.16) U13.P3 ; U13.C6 v2(31.6,42.66) U13.E6 ; U13.N4 v2(26.85,43.91) ; v2(26.04,43.16) U13.P5 ; U13.J10 v2(29.09,40.13) ; U13.M4 v2(28.09,43.66) ; U13.F5 v2(30.6,43.66)
  TOP w0.254: v1(28.45,30.87) 28,30.87 U14.12
  TOP w0.381: v1(39.37,38.42) 37.78,40.01 36.32,40.01 34.92,41.4 v1(34.92,42.55) ; R150.1 R155.1 R151.1 v1(72.64,44.45) ; 36.83,14.1 R23.1 37.21,12.89 37.47,12.64 37.47,11.05 36.83,10.41 34.86,10.41 v1(34.29,9.84) C29.1 ; R166.2 v1(73.87,26.16) ; R152.1 71.07,36.75 71.11,36.7 v1(71.95,36.7) ; R119.1 v1(31.75,33.66)
  LYR3 w0.381: v1(34.29,9.84) 35.03,9.1 41.11,9.1 42.8,10.79 54.74,10.79 v1(55.37,10.16)
  LYR4 w0.381: v1(52.58,14.86) 52.58,12.95 v1(55.37,10.16)
  LYR5_PWR w0.889: 21.49,3.71 P9.4 ; P9.4 21.49,5.18 ; P9.4 22.96,5.18 ; P9.4 22.96,3.71 ; 22.96,2.64 P9.3 21.49,2.64
  BOTTOM w0.191: R112.2 30.99,31.15 30.86,31.27 28.86,31.27 v1(28.45,30.87)
  BOTTOM w0.203: C23.1 26.29,39.07 25.92,38.71 25.88,38.71 25.8,38.63 25.64,38.63 25.27,38.27 R33.1 25.21,38.23 24.44,37.46 FB4.1 ; C23.1 26.8,39.12 27.16,38.75 U1.5 27.98,38.75 28.44,39.21 30.77,39.21 R34.1 ; C23.1 26.28,39.12
  BOTTOM w0.254: C130.1 34.8,42.42 v1(34.92,42.55) ; v2(28.09,41.16) 28.57,41.16 28.82,41.4 C128.1 29.21,40.76 29.09,40.64 v2(29.09,40.13) ; v2(30.6,43.66) 30.6,43.18 30.48,43.06 C129.1 30.87,42.42 31.11,42.66 v2(31.6,42.66) ; v2(26.04,43.16) 25.63,43.16 25.4,42.93 C127.1 ; U15.7 55.11,11.18 C155.2 55.13,10.68 U15.8
  BOTTOM w0.381: v1(50.16,45.72) 50.42,45.97 R101.1 ; v1(71.95,36.7) 71.9,36.76 P10.4 ; R11.1 7.75,18.03 8,17.78 8.51,17.78 8.76,17.53 C20.1 ; R107.1 22.99,45.85 v1(22.86,45.72) ; C126.2 v1(23.5,43.94) ; R154.1 v1(72.14,27.18) R153.1 ; P2.5 v1(34.29,9.84) ; v1(24.77,45.72) R108.1 R103.1 ; v1(73.03,24.64) 72.26,24.64 C153.1 72.39,25.27 v1(73.03,25.27) ; 9.55,17.14 v1(9.56,17.16) ; v1(28.45,30.87) 26.16,33.15 C135.1 ; R104.1 27.43,45.97 v1(27.69,45.72) ; R111.1 v1(29.21,48.26) ; R105.1 47.75,45.85 v1(47.62,45.72) ; R106.1 R109.1 42.42,45.96 v1(42.55,45.83) ; v1(45.09,45.72) R110.1 R102.1 ; R163.1 47.94,14.54 48.26,14.22 51.94,14.22 v1(52.58,14.86) ; 72.52,26.29 C154.1 ; C155.2 v1(55.37,10.16) ; R119.1 v1(31.75,33.66) ; v1(39.37,38.42) R158.1 ; R114.2 R112.2
  BOTTOM w0.635: v1(9.56,17.16) 9.58,17.14 10.86,17.14
  BOTTOM w0.762: P9.3 P9.4
  vias: v1(9.31,16.65) v1(25.53,35.67) v1(25.53,35.05)
VDD_5V: length 25.6
  TOP w0.203: U2.10 19.29,13.84
  TOP w0.254: 18.82,13.73 18.93,13.84 19.29,13.84
  LYR4 w0.762: P1.1 11.18,6.73 11.81,6.1 23.11,6.1 P9.6
  BOTTOM w0.635: P1.1 11.18,12.06 10.79,12.45 C2.2
  BOTTOM w0.762: P9.5 P9.6
VDD_ADC: length 31.5
  TOP w0.254: v1(47.32,24.41) U5.D8
  TOP w0.381: v1(45.85,20.95) 45.84,20.95 45.84,20.09 R27.1 45.09,19.34 C93.1 45.72,18.29 v1(45.85,18.41)
  LYR3 w0.381: v1(47.32,24.41) 46.71,25.02 46.23,25.02 45.85,24.64 v1(45.85,20.95)
  LYR4 w0.381: P9.32 57.15,5.08 57.15,8.38 56.13,9.4 54.1,9.4 45.85,17.65 v1(45.85,18.41)
  BOTTOM w0.381: v1(45.85,18.41) 45.85,17.65 46.35,17.14 FB2.1
VDD_CORE: length 57.4
  TOP w0.254: U5.K8 v1(47.32,30.01) U5.L7 ; U5.K6 v1(48.92,30.01) U5.L6 ; U5.M13 v1(42.52,31.61) ; v1(46.52,30.81) U5.L9 ; v1(47.32,30.81) U5.L8 ; U5.F7 v1(48.12,26.01) ; U5.G6 v1(48.92,26.81) U5.F6 ; U5.G10 v1(44.92,27.61) ; U5.N8 v1(46.52,32.41) U5.N9 ; U5.N13 v1(43.32,31.61) U5.N12 ; U5.H11 v1(44.12,27.61) ; v1(48.12,26.81) U5.G7 ; U5.J12 v1(43.32,28.41) ; U5.M11 v1(44.92,30.81) ; U5.K12 v1(44.12,30.01)
  LYR4 w0.508: 32.13,25.15 v1(32.13,24.77) ; 32.13,25.15 31.5,25.15 31.11,24.77 31.11,23.37 30.73,22.99 30.73,19.18 31.11,18.8 31.11,14.99 v1(29.21,13.08) v1(28.57,13.08) ; 32.13,25.15 v1(32.13,25.4)
  BOTTOM w0.305: v1(46.52,30.81) 45.83,30.81 C47.1 45.61,30.81 v1(44.92,30.81) ; C50.1 47.43,26.01 v1(48.12,26.01) v1(48.12,26.81) v1(48.92,26.81) ; C49.1 45.03,27.5 v1(44.92,27.61) ; v1(44.12,30.01) 43.61,29.5 C46.1 43.61,28.7 v1(43.32,28.41) v1(44.12,27.61) ; v1(40.12,30.81) 39.83,30.81 38.93,29.91 38.73,29.91 C45.1 ; v1(46.52,32.41) 46.12,32.81 45.83,32.81 C42.1 ; v1(43.32,31.61) v1(42.52,31.61) 42.52,32.3 C41.1 ; v1(48.92,30.01) v1(47.32,30.01) U5.K8 46.92,29.32 C48.1 ; C43.1 v1(47.32,30.81)
  BOTTOM w0.381: C44.1 C54.1 v1(39.32,26.81) ; C40.2 34.8,28.07 C52.1 ; C40.2 35.56,28.07 v1(35.56,27.37) 35.56,26.99 ; C40.2 34.8,28.83 C51.1 ; C53.1 34.8,25.15 C39.2 ; C39.2 34.8,25.91 C52.1 ; C39.2 35.56,25.91 v1(35.56,26.61) 35.56,26.99 ; C52.1 35.56,26.99 ; v1(28.57,13.08) v1(29.21,13.08) 29.21,13.78 L3.2 28.57,13.78 v1(28.57,13.08)
VDD_MPU: length 33.6
  TOP w0.254: U5.J13 v1(42.52,28.41) U5.H13 42.81,27.9 42.81,27.32 U5.G13 v1(42.52,26.81) U5.F13 v1(43.32,26.01) U5.F12 U5.F11 44.59,26.48 45.25,26.48 U5.F10
  TOP w0.508: v1(36.08,22.1) v1(36.08,21.46)
  TOP w0.635: 36.08,21.69 35.56,21.69 34.92,21.06 34.92,19.05 33.15,17.27 33.15,13.97 30.48,11.3 26.29,11.3
  BOTTOM w0.305: v1(43.32,26.01) 43.43,25.9 C63.1
  BOTTOM w0.381: C62.2 34.8,21.21 C64.1 ; C62.2 35.31,21.46 v1(36.08,21.46) v1(36.08,22.1) 35.43,22.1 35.18,21.84 C62.2 ; v1(42.52,28.41) 42.63,28.52 C65.1 ; 27.11,8.89 L2.2 26.48,8.89 v1(26.48,9.91) v1(27.11,9.91) 27.11,8.89
VDD_MPUON: length 10.6
  TOP w0.121: TP2.1 56.27,15.56 55.57,16.26 54.99,16.26 54.61,16.64 54.61,17.65 53.34,18.92 52.7,18.92 52.32,19.3 52.32,20.07 51.72,20.67 U5.A2
VDD_PHYA: length 16.9
  TOP w0.254: v1(22.99,27.69) 23.33,28.03 U14.1 ; v1(21.27,33.02) 21.27,32.77 21.78,32.26 21.78,32.08 22,31.87 U14.27
  BOTTOM w0.381: FB4.2 22.61,35.82 C133.2 ; R137.2 v1(10.67,29.21) ; C133.2 21.59,33.34 21.38,33.13 v1(21.27,33.02) ; C133.2 22.61,31.37 22.99,30.99 C132.1 C131.1 v1(22.99,27.69) ; R120.2 v1(18.73,29.21) ; R123.2 v1(18.73,32.07) ; R121.2 v1(18.73,30.16) ; R122.2 v1(18.73,31.11)
VDD_PLL: length 15
  TOP w0.254: U5.R10 45.32,33.62 v1(44.92,34.01) U5.R11 v1(44.12,33.21) ; v1(48.12,25.21) U5.E7 ; U5.H15 v1(40.92,27.61)
  LYR3 w0.381: v1(44.92,34.01) v1(44.12,33.21) 43.29,32.38 41.66,32.38 41.23,31.96 41.22,31.96 41.14,31.88 40.11,31.88 39.85,31.62 39.85,31.39 39.51,31.05 39.08,31.05 v1(38.52,31.61)
  BOTTOM w0.305: C94.1 v1(44.12,33.21)
  BOTTOM w0.635: FB1.2 36.26,32.07 36.72,31.61 v1(38.52,31.61)
VDD_RTC: length 5.4
  TOP w0.254: v1(48.92,24.41) U5.D6
  BOTTOM w0.121: C104.1 48.75,20.66 48.75,22.29 49.32,22.86 49.32,23.54 49.32,24.01 v1(48.92,24.41)
VDDS: length 56.7
  TOP w0.254: v1(46.52,26.01) U5.F9 ; U5.E6 v1(48.92,25.21) ; v1(43.32,30.01) U5.K13 ; U5.N6 v1(48.12,31.61) ; U5.E14 v1(41.72,25.21) ; v1(46.52,33.21) U5.P9 ; v1(41.72,33.21) U5.P14
  TOP w0.381: v1(10.92,19.56) R9.1 R8.2
  LYR5_PWR w0.305: v1(45.72,29.21) 45.41,29.52 43.81,29.52 v1(43.32,30.01)
  BOTTOM w0.121: v1(41.72,33.21) 41.4,32.89 41.17,32.89 41.09,32.81 39.67,32.81 ; 41.32,35.26 41.32,33.61
  BOTTOM w0.254: C84.1 39.27,32.41 39.67,32.81 ; 41.32,33.61 v1(41.72,33.21)
  BOTTOM w0.305: 41.32,35.26 41.32,35.91 41.32,35.91 C80.1
  BOTTOM w0.381: C80.1 41.64,36.3 41.91,36.58 41.91,37.73 42.28,38.1 44.07,38.1 44.6,37.57 46.12,37.57 46.48,37.21 46.48,36.58 46.76,36.3 C81.1 ; v1(10.92,19.56) 11.68,19.56 14.86,22.73 19.68,22.73 21.08,24.13 28.19,24.13 28.57,23.75 32.13,23.75 32.38,23.5 34.51,23.5 35.02,22.98 36.33,22.98 37.83,21.48 38.88,21.48 39.24,21.84 39.24,22.73
VDDS_DDR: length 57.1
  TOP w0.254: U5.H5 v1(49.72,28.41) U5.J5 ; v1(60.7,25.57) U12.H2 ; v1(67.1,27.97) U12.E9 ; v1(59.9,20.76) U12.N1 ; v1(61.5,27.97) U12.D2 ; U5.G5 v1(49.72,26.81) U5.F5 U5.E5 ; v1(67.1,29.57) U12.C9 ; v1(59.9,31.17) U12.A1 ; v1(60.7,30.37) U12.B2 ; v1(59.9,29.57) U12.C1 ; U5.K5 v1(49.72,30.01) U5.L5 ; v1(59.9,19.16) U12.R1 ; v1(67.1,25.57) U12.H9 ; v1(60.7,23.16) U12.K2 ; v1(67.1,19.16) U12.R9 ; v1(67.1,20.76) U12.N9 ; v1(66.3,23.16) U12.K8 ; v1(67.1,28.77) U12.D9 ; v1(59.9,27.17) U12.F1 ; v1(65.5,26.37) U12.G7 ; v1(66.3,31.17) U12.A8
  TOP w0.381: C96.2 v1(55.37,15.81) ; v1(20.76,7.11) v1(20.13,7.11) 20.13,8.06 C9.2 20.76,8.45 v1(20.76,7.11)
  BOTTOM w0.305: C97.1 49.72,30.7 v1(49.72,30.01) 49.72,29.32 C98.1 49.72,29.1 v1(49.72,28.41) 49.72,27.72 C99.1 49.72,27.5 v1(49.72,26.81) 49.72,26.12 C100.1
  BOTTOM w0.381: v1(67.1,19.16) C121.1 ; v1(52.83,20.32) v1(52.83,19.56) 53.59,19.56 C95.2 53.59,20.32 v1(52.83,20.32) ; v1(52.83,20.32) 52.2,20.32 C101.1 ; v1(59.9,29.57) C108.1 ; 66.93,31.17 C118.2 66.04,32.26 v1(65.91,32.38) ; 66.93,31.17 v1(66.3,31.17) ; 66.93,31.17 67.51,31.17 C114.1 ; v1(67.1,20.76) C120.1 ; C110.1 59.52,26.16 60.1,26.16 v1(60.7,25.57) ; v1(60.7,23.16) 60.14,22.61 59.49,22.61 C111.1 ; v1(67.1,29.57) C115.1 ; C113.1 v1(59.9,19.16) ; R6.2 18.8,7.49 19.18,7.11 v1(20.13,7.11) v1(20.76,7.11) ; v1(59.9,20.76) C112.1 ; v1(65.5,26.37) 64.7,25.57 R98.1 ; v1(67.1,27.97) C116.1 ; v1(67.1,25.57) C117.1 ; R97.1 v1(64.01,18.36) ; C119.1 67.5,24.36 v1(66.3,23.16) ; C122.2 v1(66.04,16.83) ; C107.1 v1(59.9,31.17) ; v1(55.37,15.81) 55.24,15.68 C103.1 C102.1 ; C109.1 v1(59.9,27.17)
  vias: v1(49.91,5.97) v1(50.55,5.97) v1(53.72,5.97) v1(54.36,5.97) v1(57.91,5.97) v1(58.67,5.97) v1(59.44,5.97)
12M_LOOP: length 2.9
  BOTTOM w0.121: U6.2 44.45,11.1 44.58,11.23 44.58,11.63 44.45,11.76 U6.3
12MHZ: length 50.9
  TOP w0.121: v1(64.9,34.8) 64.75,34.95 U11.27
  LYR4 w0.133: v1(60.2,12.45) 61.98,14.22 66.36,14.22 69.41,17.27 70.48,17.27 71.37,18.16 71.37,33.15 69.22,35.31 65.41,35.31 v1(64.9,34.8)
  BOTTOM w0.121: v1(60.2,12.45) 59.56,13.08 49.66,13.08 49.02,12.45 49.02,11.18 48.77,10.92 R21.2
AIN0: length 38.3
  TOP w0.121: P9.39 66.67,3.17 66.67,4.95 65.41,6.22 62.61,6.22 59.18,9.65 48.26,9.65 47.86,10.05 47.86,19.79 48.51,20.45 48.51,21.77 48.12,22.16 48.12,22.81 U5.B6
AIN1: length 32.3
  TOP w0.121: v1(48.12,23.61) U5.C7
  LYR4 w0.133: P9.40 66.29,6.1 60.71,6.1 54.1,12.7 54.1,14.73 52.45,16.38 50.67,16.38 49.66,17.4 49.66,19.81 48.51,20.95 48.51,23.22 v1(48.12,23.61)
AIN2: length 36.8
  TOP w0.121: U5.B7 47.32,22.81 47.32,22.2 48.01,21.51 48.01,20.7 47.36,20.06 47.36,9.53 47.75,9.14 58.67,9.14 62.1,5.71 63.63,5.71 64.26,5.08 64.26,3.05 P9.37
AIN3: length 33.1
  TOP w0.121: P9.38 63.88,5.97 62.36,5.97 58.93,9.4 48.01,9.4 47.61,9.79 47.61,19.93 48.27,20.58 48.27,21.63 47.72,22.18 U5.A7
AIN4: length 29.9
  TOP w0.121: U5.C8 v1(47.32,23.61)
  LYR4 w0.133: v1(47.32,23.61) 48.13,22.8 48.13,20.83 48.77,20.19 48.77,17.53 50.29,16 52.32,16 53.72,14.6 53.72,12.57 61.59,4.7 61.59,3.17 P9.33
AIN5: length 32.4
  TOP w0.121: U5.B8 46.52,22.81 46.52,22.19 46.86,21.84 46.86,9.02 47.24,8.64 58.24,8.64 62.43,4.45 P9.36
AIN6: length 35.8
  TOP w0.121: U5.A8 46.92,22.17 47.75,21.34 47.75,20.83 47.12,20.19 47.12,9.27 47.5,8.89 58.42,8.89 61.85,5.46 63.37,5.46 63.88,4.95 63.88,2.92 P9.35
AIN7: length 10.4
  TOP w0.121: U5.C9 v1(46.52,23.61)
  LYR4 w0.133: v1(48.26,17.78) 47.75,18.29 47.75,22.38 v1(46.52,23.61)
  BOTTOM w0.121: R164.1 48.77,15.68 48.58,15.88 48.58,16.51 48.39,16.7 R163.2 47.94,17.46 v1(48.26,17.78)
AM3_MMC1_CLK: length 5
  TOP w0.121: R35.1 46.86,38.86 46.67,38.67 46.67,36.45 46.52,36.29 46.52,35.61 U5.U9
AM3_MMC1_CMD: length 4.2
  TOP w0.121: R36.1 45.97,39.12 46.42,38.67 46.42,36.65 46.12,36.35 U5.V9
AM3_MMC1_DAT0: length 13.2
  TOP w0.121: U5.U7 48.12,35.61 48.12,36.44 48.26,36.58 48.26,38.54 48.39,38.67 48.39,44.63 v1(48.62,44.87)
  BOTTOM w0.121: R43.1 49.53,45.59 49.78,45.34 49.78,44.83 49.56,44.6 48.89,44.6 v1(48.62,44.87)
AM3_MMC1_DAT1: length 19
  TOP w0.121: U5.V7 47.72,36.42 48.01,36.7 48.01,38.84 48.13,38.97 48.13,44.96 48.51,45.34 48.9,45.34 49.28,45.72 49.28,48.01 49.02,48.26 46.86,48.26 46.48,47.88 46.48,46.1 v1(46.86,45.72)
  BOTTOM w0.121: R44.1 v1(46.86,45.72)
AM3_MMC1_DAT2: length 36.9
  TOP w0.121: v1(47.32,34.01) U5.R8
  LYR3 w0.121: v1(47.32,34.01) 46.92,34.41 46.92,35.05 46.92,35.05
  LYR3 w0.133: v1(34.92,47.24) 35.56,46.61 39.62,46.61 40.13,46.1 40.13,44.7 46.23,38.61 46.23,35.81 46.92,35.12 46.92,35.05
  LYR4 w0.133: v1(26.54,45.72) 26.54,46.22 26.41,46.35 24.04,46.35 23.91,46.49 23.91,46.84 24.04,46.97 34.65,46.97 v1(34.92,47.24)
  BOTTOM w0.121: R168.1 v1(26.54,45.72)
AM3_MMC1_DAT3: length 29.6
  TOP w0.121: v1(47.32,34.81) U5.T8
  LYR3 w0.133: v1(47.32,34.81) 47.32,35.23 46.49,36.06 46.49,38.86 40.51,44.83 40.51,46.35 39.88,46.99 36.2,46.99 v1(35.43,47.75)
  LYR4 w0.133: v1(35.43,47.75) 35.43,46.99 35.05,46.61 29.46,46.61 v1(28.58,45.72)
  BOTTOM w0.121: R169.1 28.32,45.98 v1(28.58,45.72)
AM3_MMC1_DAT4: length 19.9
  TOP w0.121: U5.U8 47.32,35.61 47.32,36.4 47.75,36.83 47.75,43.81 47.24,44.32 47.24,44.96 47.36,45.09 47.75,45.09 48.13,45.47 48.13,46.1 47.88,46.35 47.24,46.35 47.12,46.48 47.12,47.63 47.24,47.75 47.5,47.75 47.62,47.63 47.62,46.98 47.75,46.86 48.01,46.86 48.13,46.98 48.13,47.63 48.25,47.75 48.51,47.75 48.64,47.63 v1(48.64,45.83)
  BOTTOM w0.121: R170.1 v1(48.64,45.83)
AM3_MMC1_DAT5: length 13.5
  TOP w0.121: U5.V8 46.92,38.41 47.37,38.86 47.37,43.81 46.74,44.45 46.74,45.24 v1(46.25,45.72)
  BOTTOM w0.121: v1(46.25,45.72) 45.75,45.21 44.83,45.21 44.2,45.85 R171.1
AM3_MMC1_DAT6: length 36.1
  TOP w0.121: v1(46.52,34.01) U5.R9
  LYR3 w0.133: v1(46.52,34.01) 45.85,34.68 43.81,36.72 43.81,38.99 43.18,39.62 43.18,40.64 41.53,42.29 40.64,42.29 40.13,42.8 40.13,43.69 38.61,45.21 34.92,45.21 34.15,45.99 34.15,47.48 v1(34.42,47.75)
  LYR4 w0.133: v1(22.1,45.72) 23.75,47.37 34.04,47.37 v1(34.42,47.75)
  BOTTOM w0.121: R172.1 v1(22.1,45.72)
AM3_MMC1_DAT7: length 31.4
  TOP w0.121: v1(46.52,34.81) U5.T9
  LYR3 w0.133: v1(34.8,45.97) 38.35,45.97 40.51,43.81 40.51,42.93 40.77,42.67 41.66,42.67 43.56,40.77 43.56,39.75 44.32,38.99 44.32,37.01 45.94,35.39 v1(46.52,34.81)
  LYR4 w0.133: v1(23.88,45.72) 24.36,45.24 29.11,45.24 29.84,45.97 v1(34.8,45.97)
  BOTTOM w0.121: R173.1 v1(23.88,45.72)
B_UART0_RX: length 13.6
  TOP w0.121: R165.1 46.35,7.24 47.12,6.48 49.02,6.48 J1.4
  BOTTOM w0.121: J1.4 52.2,9.65 52.2,10.92 51.94,11.18 U15.2
B_UART0_TX: length 5.2
  BOTTOM w0.121: U15.3 51.95,11.68 52.45,11.18 52.45,8.89 52.7,8.64 J1.5
CAP_VBB_MPU: length 4.2
  TOP w0.121: U5.C10 44.93,23.62 v1(44.92,23.61)
  BOTTOM w0.121: C91.1 45.4,22.42 44.92,22.9 v1(44.92,23.61)
CAP_VDD_SRAM_CORE: length 5.2
  TOP w0.121: U5.D9 v1(46.52,24.41)
  BOTTOM w0.121: C89.1 46.35,22.48 46.92,23.04 46.92,24.01 v1(46.52,24.41)
CAP_VDD_SRAM_MPU: length 5
  TOP w0.121: v1(44.12,24.41) U5.D11
  BOTTOM w0.121: C90.1 44.52,20.26 44.52,24.01 v1(44.12,24.41)
CLKOUT2: length 57.6
  BOTTOM w0.121: P9.41 71.63,3.05 71.63,4.83 69.98,6.48 65.15,6.48 61.72,9.91 61.72,12.83 60.71,13.84 46.89,13.84 46.7,13.65 42.23,13.65 41.59,14.29 41.59,17.59 42.55,18.54 R20.1 R19.2 41.08,19.68 41.08,20.64 40.89,20.83 40.13,20.83 39.88,20.57 36.26,20.57 35.67,19.98 35.67,17.8 36,17.46 P2.18
CLKOUT_SRC: length 5.1
  TOP w0.121: U5.D14 v1(41.72,24.41)
  BOTTOM w0.121: R19.1 41.59,22.99 41.32,23.26 41.32,24.01 v1(41.72,24.41)
CRS: length 2.7
  TOP w0.121: U14.14 28.31,31.87 28.68,32.24 29.51,32.24 R139.2
DDR_A0: length 23.9
  TOP w0.121: v1(61.5,20.76) U12.N3 ; U5.F3 v1(51.32,26.01)
  LYR3 w0.133: v1(53.85,23.11) 53.34,23.11 53.21,22.99 53.21,21.21 54.86,19.56 54.86,19.3 57.02,17.14 61.59,17.14 62.36,17.91 62.36,20.7 61.98,21.08 61.82,21.08 v1(61.5,20.76)
  BOTTOM w0.121: v1(51.32,26.01) 51.73,26.42 52.32,26.42 52.58,26.16 52.58,24.38 v1(53.85,23.11)
DDR_A1: length 24.1
  TOP w0.121: U5.H1 54.54,28.01 56.58,25.97 57.72,25.97 58.93,24.77 v1(58.93,23.88) ; v1(65.5,19.96) U12.P7
  LYR3 w0.121: 60.2,23.87 60.5,23.57 61.67,23.57
  LYR3 w0.133: 60.2,23.87 58.93,23.87 v1(58.93,23.88) ; 61.67,23.57 61.78,23.57 62.23,23.11 62.61,23.11 63.88,21.84 63.88,20.83 63.5,20.45 63.5,18.9 63.63,18.77 64.39,18.77 64.52,18.9 64.52,19.05 64.39,19.18 64.01,19.18 63.88,19.3 63.88,20.19 64.01,20.32 64.14,20.32 64.26,20.19 64.26,19.68 64.39,19.56 64.64,19.56 64.77,19.68 64.77,20.19 64.9,20.32 65.14,20.32 v1(65.5,19.96)
DDR_A2: length 23.9
  TOP w0.121: U5.E4 v1(50.52,25.21) ; v1(61.5,19.96) U12.P3
  LYR3 w0.121: v1(61.5,19.96) 61.1,20.36 61.1,22.09
  LYR3 w0.133: v1(50.52,25.21) 50.52,24.98 51.12,24.38 54.36,24.38 55.12,25.15 55.12,26.04 54.26,26.9 54.26,27.08 54.5,27.32 54.72,27.32 56.64,25.4 56.64,24.38 56.77,24.26 57.4,24.26 57.51,24.16 57.51,23.72 57.4,23.62 56.77,23.62 56.64,23.5 56.64,22.1 56.77,21.97 59.05,21.97 59.44,22.35 60.83,22.35 61.1,22.09
DDR_A3: length 24
  TOP w0.121: v1(51.32,23.61) U5.C3 ; v1(60.7,20.76) U12.N2
  LYR3 w0.121: 59.61,21.16 60.3,21.16 v1(60.7,20.76)
  LYR3 w0.133: 59.61,21.16 59.56,21.21 56.01,21.21 55.88,21.34 55.88,24.43 55.8,24.51 55.58,24.51 55.5,24.43 55.5,22.2 55.42,22.12 55.07,22.12 54.99,22.05 54.99,21.67 54.91,21.59 54.69,21.59 54.61,21.67 54.61,22.05 54.53,22.12 54.37,22.12 54.29,22.2 54.29,22.4 54.37,22.48 55.04,22.48 55.12,22.56 55.12,22.78 55.04,22.86 54.37,22.86 54.29,22.94 54.29,23.16 54.37,23.24 55.04,23.24 55.12,23.32 55.12,23.53 55.04,23.61 52.96,23.61 52.83,23.48 52.83,22.35 52.7,22.23 52.45,22.23 52.32,22.35 52.32,23.48 52.2,23.61 v1(51.32,23.61)
DDR_A4: length 23.9
  TOP w0.121: v1(56.13,16.26) 56.52,16.64 56.52,17.02 53.72,19.81 53.72,20.57 52.96,21.34 52.96,22.53 52.68,22.81 52.36,22.81 52.12,23.05 52.12,23.61 U5.C2 ; v1(66.3,19.96) U12.P8
  LYR3 w0.121: 65.28,19.56 65.9,19.56 v1(66.3,19.96)
  LYR3 w0.133: v1(56.13,16.26) 56.39,16 62.36,16 63.12,16.76 64.77,16.76 65.02,17.02 65.02,19.3 65.28,19.56
DDR_A5: length 23.9
  TOP w0.121: v1(53.85,22.1) 53.47,22.1 53.34,22.23 53.34,22.61 52.74,23.21 U5.B1 ; v1(60.7,19.96) U12.P2
  LYR3 w0.121: 61.09,18.16 61.1,18.17 61.1,19.56 v1(60.7,19.96)
  LYR3 w0.133: 61.09,18.16 60.83,17.91 59.44,17.91 59.31,18.03 59.31,20.7 59.18,20.83 57.78,20.83 57.66,20.7 57.66,18.41 57.53,18.29 56.9,18.29 56.64,18.54 56.64,20.7 56.52,20.83 56.26,20.83 56.13,20.7 56.13,19.68 56.01,19.56 55.75,19.56 55.63,19.68 55.63,21.64 55.55,21.72 55.32,21.72 55.24,21.64 55.24,21.03 55.17,20.95 54.54,20.95 54.29,21.2 54.29,21.65 v1(53.85,22.1)
DDR_A6: length 24.1
  TOP w0.121: v1(49.72,24.41) U5.D5 ; v1(66.3,19.16) U12.R8
  BOTTOM w0.121: v1(49.72,24.41) 50.12,24.81 51.39,24.81 53.59,22.61 53.98,22.61 55.37,21.21 55.37,18.67 57.28,16.76 64.52,16.76 65.9,18.15 65.9,18.76 v1(66.3,19.16)
DDR_A7: length 24.1
  TOP w0.121: v1(60.7,19.16) U12.R2 ; v1(57.15,19.91) 57.63,19.43 58.17,19.43 58.29,19.3 58.29,18.03 58.17,17.91 57.4,17.91 55.63,19.68 55.63,23.88 54.36,25.15 54.36,25.78 54.13,26.01 52.12,26.01 U5.E2
  BOTTOM w0.121: v1(60.7,19.16) U12.R2 62.23,19.56 62.36,19.69 62.36,20.24 62.23,20.36 59.61,20.36 59.16,19.91 v1(57.15,19.91)
DDR_A8: length 23.9
  TOP w0.121: v1(50.52,24.41) U5.D4 ; v1(66.3,18.36) U12.T8
  BOTTOM w0.121: v1(66.3,18.36) 66.3,18.04 64.64,16.38 57.15,16.38 54.99,18.54 54.99,20.68 54.61,21.06 52.19,21.06 51.94,21.31 51.94,23.75 51.28,24.41 v1(50.52,24.41)
DDR_A9: length 24
  TOP w0.121: U5.C1 53.09,23.44 53.09,23.31 53.79,22.61 54.1,22.61 54.25,22.46 54.25,20.95 54.13,20.83 53.97,20.83 53.85,20.95 v1(53.85,21.46) ; v1(61.5,19.16) U12.R3
  LYR3 w0.133: v1(61.5,19.16) 61.5,19.43 61.63,19.56 61.85,19.56 61.98,19.43 61.98,18.03 61.47,17.53 58.93,17.53 58.8,17.65 58.8,20.32 58.67,20.45 58.29,20.45 58.17,20.32 58.17,17.65 58.04,17.53 57.15,17.53 55.24,19.43 55.24,20.32 54.99,20.57 54.36,20.57 53.85,21.08 v1(53.85,21.46)
DDR_A10: length 24
  TOP w0.121: v1(65.5,22.36) U12.L7 ; U5.F4 v1(50.52,26.01)
  LYR3 w0.121: 51.68,26.41 50.92,26.41 v1(50.52,26.01)
  LYR3 w0.133: v1(65.5,22.36) 65.79,22.65 65.79,22.86 65.66,22.99 64.77,22.99 64.64,23.11 64.64,23.37 64.77,23.5 65.66,23.5 65.79,23.62 65.79,23.88 65.66,24 64.39,24 62.36,26.04 59.31,26.04 57.72,27.62 56.83,27.62 55.75,28.71 52.58,28.71 52.2,28.32 52.2,26.92 51.68,26.41
DDR_A11: length 23.9
  TOP w0.121: v1(65.5,19.16) U12.R7 ; v1(53.85,26.81) 52.12,26.81 U5.F2
  BOTTOM w0.121: v1(53.85,26.81) 53.34,26.3 53.34,24.77 54.61,23.5 55.88,23.5 56.13,23.24 56.13,18.92 57.53,17.53 64.14,17.53 64.77,18.16 64.77,18.91 65.02,19.16 v1(65.5,19.16)
DDR_A12: length 24.1
  TOP w0.121: v1(51.32,25.21) U5.E3 ; v1(65.5,20.76) U12.N7
  LYR3 w0.133: v1(65.5,20.76) 63.88,22.38 63.88,23.37 62.23,25.02 61.47,25.02 61.22,24.77 59.56,24.77 57.91,26.42 56.64,26.42 55.12,27.94 53.21,27.94 52.96,27.69 52.96,26.29 53.21,26.04 54.1,26.04 54.36,25.78 54.36,25.4 54.1,25.15 51.38,25.15 v1(51.32,25.21)
DDR_A13: length 24
  TOP w0.121: v1(61.5,18.36) U12.T3 ; U5.H3 v1(51.32,27.61)
  BOTTOM w0.121: v1(51.32,27.61) 53.92,27.61 54.36,27.18 54.36,24.26 54.74,23.88 56.26,23.88 56.52,23.62 56.52,19.05 57.66,17.91 63.37,17.91 63.5,18.03 63.5,18.24 63.37,18.36 v1(61.5,18.36)
DDR_A14: length 24
  TOP w0.121: v1(50.52,27.61) U5.H4 ; v1(65.5,18.36) U12.T7
  BOTTOM w0.121: v1(50.52,27.61) 50.52,27.58 50.9,27.21 52.55,27.21 52.96,26.8 52.96,24.64 55.75,21.84 55.75,18.8 57.4,17.14 64.28,17.14 v1(65.5,18.36)
DDR_A15: length 24.1
  TOP w0.121: U5.D3 51.32,24.41 53.57,24.41 54.61,23.37 54.61,19.43 57.15,16.89 63.88,16.89 64.52,17.53 64.52,21.38 U12.M7
DDR_BA0: length 24.1
  TOP w0.121: v1(60.7,21.56) U12.M2 ; U5.C4 v1(50.52,23.61)
  LYR3 w0.121: 50.12,22.48 50.12,23.48 50.25,23.61 v1(50.52,23.61) ; 50.92,23.74 50.92,22.48
  LYR3 w0.133: 50.92,23.74 50.92,23.89 51.05,24.02 54.5,24.02 55.5,25.02 55.5,25.65 55.6,25.75 55.78,25.75 56.26,25.27 56.26,21.97 56.64,21.59 59.18,21.59 59.56,21.97 60.57,21.97 60.7,21.84 v1(60.7,21.56) ; 50.92,22.48 51.05,22.35 51.44,22.35 51.56,22.23 51.56,21.46 51.44,21.34 51.18,21.34 51.05,21.46 51.05,21.84 50.93,21.97 50.67,21.97 50.55,21.84 50.55,21.46 50.42,21.34 50.25,21.34 50.12,21.46 50.12,22.48
DDR_BA1: length 24.1
  TOP w0.121: v1(66.3,20.76) U12.N8 ; U5.E1 v1(53.85,25.61)
  LYR3 w0.133: v1(53.85,25.61) 52.62,25.61 52.32,25.91 52.32,26.29 52.58,26.54 52.58,28.07 52.83,28.32 55.37,28.32 56.93,26.76 58.08,26.76 59.69,25.15 61.09,25.15 61.21,25.27 61.21,25.53 61.34,25.65 62.1,25.65 64.23,23.52 64.23,22.63 65.05,21.82 65.66,21.82 65.82,21.65 65.82,21.24 v1(66.3,20.76)
DDR_BA2: length 24.1
  TOP w0.121: v1(51.32,22.81) U5.B3 ; v1(61.5,21.56) U12.M3
  LYR3 w0.133: v1(51.32,22.81) 51.63,23.11 51.82,23.11 51.94,22.99 51.94,20.83 52.07,20.7 52.26,20.7 52.39,20.83 52.39,21.08 52.51,21.21 52.7,21.21 54.48,19.43 54.48,19.18 56.9,16.76 61.98,16.76 62.74,17.53 62.74,20.83 62.48,21.08 62.48,21.34 62.74,21.59 62.74,21.97 62.48,22.23 62.23,22.23 62.1,22.1 62.1,21.69 61.98,21.56 v1(61.5,21.56)
DDR_CASN: length 24
  TOP w0.121: v1(61.5,23.16) U12.K3 ; v1(57.15,22.48) 57.15,21.72 57.28,21.59 58.17,21.59 58.29,21.46 58.29,20.95 58.17,20.83 58.04,20.83 57.91,20.7 57.91,20.45 58.04,20.32 58.17,20.32 58.29,20.19 58.29,19.94 58.17,19.81 57.68,19.81 57.55,19.94 57.55,21.21 57.42,21.34 56.77,21.34 56.64,21.21 56.64,19.81 56.52,19.68 56.13,19.68 56.01,19.81 56.01,24.64 55.88,24.77 55.37,24.77 54.74,25.4 54.74,26.16 54.48,26.41 U5.F1
  LYR3 w0.133: v1(61.5,23.16) 61.07,22.73 59.31,22.73 59.05,22.48 v1(57.15,22.48)
DDR_CKE: length 25.1
  TOP w0.121: U5.G3 v1(51.32,26.81) ; v1(67.1,23.16) U12.K9
  LYR3 w0.133: v1(51.32,26.81) 51.82,27.3 51.82,28.83 51.69,28.96 51.18,28.96 51.05,29.08 51.05,29.34 51.18,29.46 52.83,29.46 53.21,29.08 55.88,29.08 57.02,27.94 57.91,27.94 59.44,26.42 62.61,26.42 64.64,24.38 67.18,24.38 67.31,24.26 67.31,23.37 v1(67.1,23.16)
  BOTTOM w0.121: R96.2 v1(67.1,23.16)
DDR_CLK: length 24
  TOP w0.095: U12.J7 64.94,24.2 64.74,24.2 63.75,23.22 63.75,19.7 61.58,17.53 57.42,17.53 55.27,19.67 55.27,23.72 53.8,25.2 52.36,25.2 51.98,24.81 U5.D2
DDR_CLKN: length 24
  TOP w0.095: U5.D1 52.63,24.92 53.68,24.92 54.99,23.61 54.99,19.56 57.3,17.25 61.7,17.25 64.03,19.58 64.03,23.1 64.85,23.92 65.37,23.92 65.48,23.82 65.48,23.67 65.37,23.56 U12.K7
DDR_CSN: length 23.9
  TOP w0.121: U5.H2 52.12,28.41 54.65,28.41 56.71,26.35 57.85,26.35 59.44,24.77 59.44,23.44 59.36,23.37 58.88,23.37 58.8,23.29 58.8,22.09 59.05,21.84 59.05,18.41 59.18,18.29 59.31,18.29 59.44,18.41 59.44,21.97 59.18,22.23 59.18,22.78 59.26,22.86 59.49,22.86 59.56,22.78 59.56,22.44 59.64,22.36 60.7,22.36 U12.L2
DDR_D0: length 23.3
  TOP w0.121: v1(51.32,31.61) U5.M3 ; v1(62.3,27.97) U12.E3
  LYR3 w0.133: v1(62.3,27.97) 62.3,29.72 62.43,29.84 62.87,29.84 62.99,29.72 62.99,27.43 63.12,27.3 63.63,27.3 63.75,27.43 63.75,29.59 60.45,32.89 52.96,32.89 51.68,31.61 v1(51.32,31.61)
DDR_D1: length 23.3
  TOP w0.121: v1(65.5,27.17) U12.F7 ; v1(50.52,31.61) U5.M4
  LYR3 w0.121: 66.47,25.16 66.7,25.39 66.7,25.74 66.7,26.53 66.47,26.77 65.9,26.77 v1(65.5,27.17) ; 52.78,30.41 51.16,30.41 50.92,30.64 50.92,31.21 v1(50.52,31.61)
  LYR3 w0.133: 66.47,25.16 66.08,24.77 64.89,24.77 62.9,26.76 59.6,26.76 57.4,28.96 56.77,28.96 56.26,29.46 53.72,29.46 52.78,30.41
DDR_D2: length 23.3
  TOP w0.121: U5.N1 55.49,32.01 55.88,31.62 57.02,31.62 57.15,31.75 57.15,32.64 57.02,32.77 54.86,32.77 54.74,32.89 54.74,33.15 54.86,33.27 61.09,33.27 61.21,33.15 61.21,32.13 62.73,30.61 62.73,27.43 62.47,27.17 61.98,27.17 61.98,27.17 61.5,27.17 U12.F2
DDR_D3: length 23.3
  TOP w0.121: v1(56.13,32.13) 55.86,32.41 52.12,32.41 U5.N2 ; v1(66.3,27.17) U12.F8
  BOTTOM w0.121: v1(56.13,32.13) 60.83,32.13 62.36,30.61 62.36,29.08 63.18,28.26 63.18,27.69 63.31,27.56 63.5,27.56 63.63,27.69 63.63,28.57 63.75,28.7 64.01,28.7 64.14,28.57 64.14,27.69 64.26,27.56 64.52,27.56 64.64,27.69 64.64,28.57 64.77,28.7 65.58,28.7 65.91,28.37 66.5,28.37 66.7,28.17 66.7,27.57 v1(66.3,27.17)
DDR_D4: length 23.3
  TOP w0.121: U12.H3 63.52,25.17 64.26,25.91 64.26,31.75 63.37,32.64 v1(62.36,32.64) ; U5.N3 v1(51.32,32.41)
  LYR3 w0.133: v1(62.36,32.64) 61.34,33.66 52.58,33.66 51.33,32.41 v1(51.32,32.41)
DDR_D5: length 23.3
  TOP w0.121: U5.N4 v1(50.52,32.41) ; v1(66.3,25.57) U12.H8
  LYR3 w0.121: v1(50.52,32.41) 50.92,32.01 51.57,32.01
  LYR3 w0.133: 51.57,32.01 52.83,33.27 60.71,33.27 64.26,29.72 64.26,26.04 65.15,25.15 65.88,25.15 v1(66.3,25.57)
DDR_D6: length 23.3
  TOP w0.121: U12.G2 61.5,25.56 63.41,25.56 63.88,26.04 63.88,31.24 v1(62.99,32.13) ; U5.P3 v1(51.32,33.21)
  LYR3 w0.133: v1(51.32,33.21) 51.63,33.21 52.45,34.04 61.59,34.04 62.99,32.64 v1(62.99,32.13)
DDR_D7: length 23.3
  TOP w0.121: v1(65.5,25.57) U12.H7 ; U5.P4 v1(50.52,33.21)
  LYR3 w0.121: v1(50.52,33.21) 50.92,33.61 51.52,33.61
  LYR3 w0.133: 51.52,33.61 52.3,34.39 61.87,34.39 64.77,31.5 64.77,26.3 v1(65.5,25.57)
DDR_D8: length 20.3
  TOP w0.121: U12.D7 64.64,27.91 64.64,24.77 62.99,23.11 62.48,23.11 62.36,23.24 62.36,24.64 62.23,24.77 59.94,24.77 59.37,25.34 59.37,26.23 58.86,26.73 56.83,26.73 54.76,28.81 U5.J1
DDR_D9: length 20.3
  TOP w0.121: v1(61.5,29.57) U12.C3 ; v1(56.13,29.97) 55.77,29.61 U5.K1
  LYR3 w0.133: v1(61.5,29.57) 61.5,28.83 61.37,28.7 59.31,28.7 59.18,28.83 59.18,32 59.05,32.13 58.55,32.13 58.42,32 58.42,29.84 58.29,29.72 57.78,29.72 57.66,29.84 57.66,32 57.53,32.13 56.77,32.13 56.64,32 56.64,30.1 56.52,29.97 v1(56.13,29.97)
DDR_D10: length 20.3
  TOP w0.121: v1(66.3,29.57) U12.C8 ; v1(53.85,30.01) 52.12,30.01 U5.K2
  BOTTOM w0.121: v1(53.85,30.01) 54.32,30.01 54.48,29.84 55.12,29.84 55.24,29.97 55.24,32.13 55.75,32.64 60.83,32.64 62.74,30.73 62.74,29.34 62.99,29.08 65.82,29.08 v1(66.3,29.57)
DDR_D11: length 20.2
  TOP w0.121: v1(51.32,30.01) U5.K3 ; v1(60.7,29.57) U12.C2
  BOTTOM w0.121: v1(51.32,30.01) 51.56,30.01 51.69,29.88 51.69,29.59 51.56,29.46 50.55,29.46 50.42,29.34 50.42,29.08 50.55,28.96 57.53,28.96 57.66,28.83 57.66,28.07 57.78,27.94 60.07,27.94 60.2,28.07 60.2,28.32 60.07,28.45 58.17,28.45 58.04,28.57 58.04,28.83 58.17,28.96 60.57,28.96 60.7,29.08 v1(60.7,29.57)
DDR_D12: length 20.2
  TOP w0.121: U5.K4 v1(50.52,30.01) ; v1(65.5,31.17) U12.A7
  BOTTOM w0.121: v1(50.52,30.01) 50.92,30.41 51.94,30.41 52.07,30.28 52.07,30.16 52.2,30.04 52.45,30.04 52.58,30.16 52.58,31.75 54.55,33.72 63.31,33.72 65.5,31.53 v1(65.5,31.17)
DDR_D13: length 20.2
  TOP w0.121: v1(51.32,30.81) U5.L3 ; v1(60.7,31.17) U12.A2
  LYR3 w0.133: v1(51.32,30.81) 51.64,30.81 52.07,31.24 54.23,31.24 54.36,31.11 54.36,30.1 54.48,29.97 55.5,29.97 55.63,30.1 55.63,31.75 55.5,31.88 53.21,31.88 53.09,32 53.09,32.41 53.21,32.54 60.17,32.54 60.71,32 60.71,31.17 v1(60.7,31.17)
DDR_D14: length 20.3
  TOP w0.121: U5.L4 v1(50.52,30.81) ; v1(66.3,30.37) U12.B8
  BOTTOM w0.121: v1(50.52,30.81) 50.92,31.21 51.53,31.21 54.36,34.04 63.5,34.04 65.9,31.64 65.9,30.77 v1(66.3,30.37)
DDR_D15: length 20.1
  TOP w0.121: U12.A3 60.03,32.64 58.04,32.64 57.91,32.51 57.91,32.26 58.04,32.13 59.31,32.13 59.44,32 59.44,31.75 59.31,31.62 58.04,31.62 57.91,31.5 57.91,31.24 58.04,31.11 59.31,31.11 59.44,30.99 59.44,30.73 59.31,30.61 55.75,30.61 55.63,30.48 55.63,30.23 55.5,30.1 54.48,30.1 54.36,30.23 54.36,30.61 54.48,30.73 54.86,30.73 54.99,30.86 54.99,31.08 54.86,31.21 53.34,31.21 U5.M1
DDR_DQM0: length 23.3
  TOP w0.121: U5.M2 52.12,31.61 55.26,31.61 55.7,31.17 v1(56.13,31.17) ; v1(65.5,27.97) U12.E7
  BOTTOM w0.121: v1(65.5,27.97) 65.15,27.97 65.02,27.84 65.02,27.3 64.9,27.18 62.87,27.18 62.74,27.3 62.74,28.19 61.98,28.96 61.98,30.48 60.71,31.75 56.77,31.75 56.64,31.62 56.64,29.59 56.52,29.46 55.75,29.46 55.63,29.59 55.63,31.04 55.75,31.17 v1(56.13,31.17)
